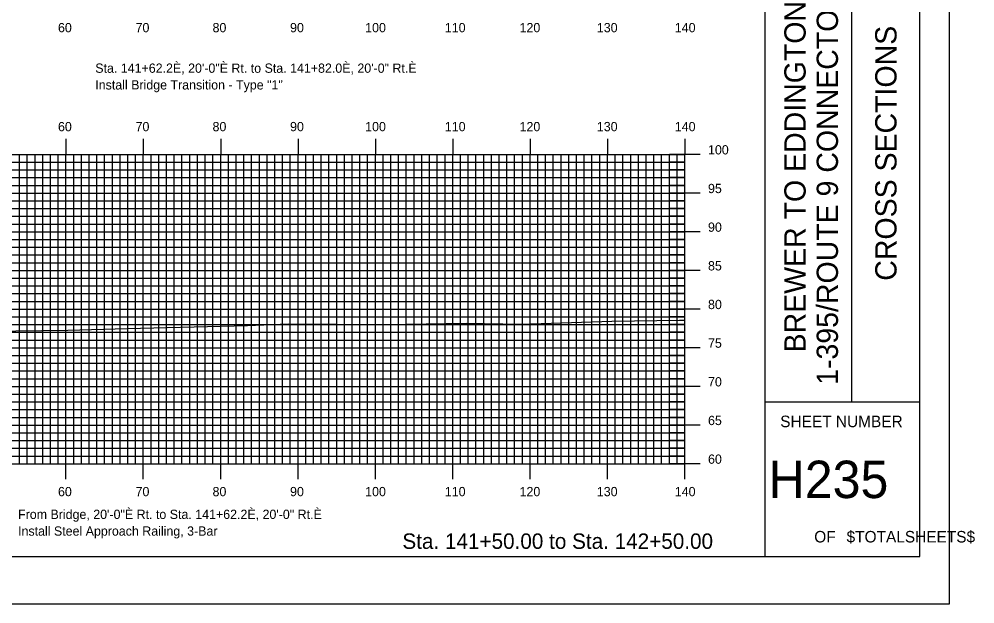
# Model space of a CAD drawing. Extents: x 1776744 to 1777088, y 442591 to 442811.
# Drawn here: x 1776964.2 to 1777087.7, y 442590.5 to 442666.2 of the extents above; entities that cross this region are included whole.
import ezdxf

# ---------------------------------------------------------------- set-up
doc = ezdxf.new("R2010")
doc.units = 0
for name, color, linetype in [('ANNOTATION', 7, 'Continuous'), ('BORDER', 7, 'Continuous'), ('H_V ANNOTATION', 7, 'Continuous'), ('MAJOR', 7, 'Continuous'), ('MINOR', 7, 'Continuous'), ('PLOT BOUNDARY', 7, 'Continuous'), ('S_Roadway_Centerline', 7, 'Continuous')]:
    doc.layers.add(name, color=color, linetype=linetype)

msp = doc.modelspace()

# ---------------------------------------------------------------- linework, layer by layer
at = {"layer": 'BORDER'}
for p, q in [((1777060.65, 442596.67), (1777060.65, 442806.67)), ((1777071.83, 442616.67), (1777071.83, 442686.67)), ((1777060.65, 442616.67), (1777080.65, 442616.67))]:
    msp.add_line(p, q, dxfattribs=at)
msp.add_lwpolyline([(1776760.65, 442596.67), (1777080.65, 442596.67), (1777080.65, 442806.67), (1776760.65, 442806.67)], close=True, dxfattribs=at)
at = {"layer": 'MAJOR'}
for p, q in [((1776970.25, 442650.67), (1776970.25, 442648.67)), ((1776980.25, 442650.67), (1776980.25, 442648.67)), ((1776990.25, 442650.67), (1776990.25, 442648.67)), ((1777000.25, 442650.67), (1777000.25, 442648.67)), ((1777010.25, 442650.67), (1777010.25, 442648.67)), ((1777020.25, 442650.67), (1777020.25, 442648.67)), ((1777030.25, 442650.67), (1777030.25, 442648.67)), ((1777040.25, 442650.67), (1777040.25, 442648.67)), ((1777050.25, 442650.67), (1777050.25, 442648.67)), ((1776770.25, 442648.67), (1777050.25, 442648.67)), ((1776770.25, 442648.67), (1777050.25, 442648.67)), ((1776970.25, 442608.67), (1776970.25, 442648.67)), ((1776980.25, 442608.67), (1776980.25, 442648.67)), ((1776990.25, 442608.67), (1776990.25, 442648.67)), ((1777000.25, 442608.67), (1777000.25, 442648.67)), ((1777010.25, 442608.67), (1777010.25, 442648.67)), ((1777020.25, 442608.67), (1777020.25, 442648.67)), ((1777030.25, 442608.67), (1777030.25, 442648.67)), ((1777040.25, 442608.67), (1777040.25, 442648.67)), ((1777052.25, 442648.67), (1777048.25, 442648.67)), ((1777050.25, 442608.67), (1777050.25, 442648.67)), ((1777050.25, 442608.67), (1777050.25, 442648.67)), ((1776770.25, 442643.67), (1777050.25, 442643.67)), ((1777052.25, 442643.67), (1777048.25, 442643.67)), ((1776770.25, 442638.67), (1777050.25, 442638.67)), ((1777052.25, 442638.67), (1777048.25, 442638.67)), ((1776770.25, 442633.67), (1777050.25, 442633.67)), ((1777052.25, 442633.67), (1777048.25, 442633.67)), ((1776770.25, 442628.67), (1777050.25, 442628.67)), ((1777052.25, 442628.67), (1777048.25, 442628.67)), ((1776770.25, 442623.67), (1777050.25, 442623.67)), ((1777052.25, 442623.67), (1777048.25, 442623.67)), ((1776770.25, 442618.67), (1777050.25, 442618.67)), ((1777052.25, 442618.67), (1777048.25, 442618.67)), ((1776770.25, 442613.67), (1777050.25, 442613.67)), ((1777052.25, 442613.67), (1777048.25, 442613.67)), ((1776770.25, 442608.67), (1777050.25, 442608.67)), ((1776770.25, 442608.67), (1777050.25, 442608.67)), ((1776970.25, 442606.66), (1776970.25, 442608.67)), ((1776980.25, 442606.66), (1776980.25, 442608.67)), ((1776990.25, 442606.66), (1776990.25, 442608.67)), ((1777000.25, 442606.66), (1777000.25, 442608.67)), ((1777010.25, 442606.66), (1777010.25, 442608.67)), ((1777020.25, 442606.66), (1777020.25, 442608.67)), ((1777030.25, 442606.66), (1777030.25, 442608.67)), ((1777040.25, 442606.66), (1777040.25, 442608.67)), ((1777052.25, 442608.67), (1777048.25, 442608.67)), ((1777050.25, 442606.66), (1777050.25, 442608.67))]:
    msp.add_line(p, q, dxfattribs=at)
at = {"layer": 'MINOR'}
for p, q in [((1776964.25, 442608.67), (1776964.25, 442648.67)), ((1776965.25, 442608.67), (1776965.25, 442648.67)), ((1776966.25, 442608.67), (1776966.25, 442648.67)), ((1776967.25, 442608.67), (1776967.25, 442648.67)), ((1776968.25, 442608.67), (1776968.25, 442648.67)), ((1776969.25, 442608.67), (1776969.25, 442648.67)), ((1776971.25, 442608.67), (1776971.25, 442648.67)), ((1776972.25, 442608.67), (1776972.25, 442648.67)), ((1776973.25, 442608.67), (1776973.25, 442648.67)), ((1776974.25, 442608.67), (1776974.25, 442648.67)), ((1776975.25, 442608.67), (1776975.25, 442648.67)), ((1776976.25, 442608.67), (1776976.25, 442648.67)), ((1776977.25, 442608.67), (1776977.25, 442648.67)), ((1776978.25, 442608.67), (1776978.25, 442648.67)), ((1776979.25, 442608.67), (1776979.25, 442648.67)), ((1776981.25, 442608.67), (1776981.25, 442648.67)), ((1776982.25, 442608.67), (1776982.25, 442648.67)), ((1776983.25, 442608.67), (1776983.25, 442648.67)), ((1776984.25, 442608.67), (1776984.25, 442648.67)), ((1776985.25, 442608.67), (1776985.25, 442648.67)), ((1776986.25, 442608.67), (1776986.25, 442648.67)), ((1776987.25, 442608.67), (1776987.25, 442648.67)), ((1776988.25, 442608.67), (1776988.25, 442648.67)), ((1776989.25, 442608.67), (1776989.25, 442648.67)), ((1776991.25, 442608.67), (1776991.25, 442648.67)), ((1776992.25, 442608.67), (1776992.25, 442648.67)), ((1776993.25, 442608.67), (1776993.25, 442648.67)), ((1776994.25, 442608.67), (1776994.25, 442648.67)), ((1776995.25, 442608.67), (1776995.25, 442648.67)), ((1776996.25, 442608.67), (1776996.25, 442648.67)), ((1776997.25, 442608.67), (1776997.25, 442648.67)), ((1776998.25, 442608.67), (1776998.25, 442648.67)), ((1776999.25, 442608.67), (1776999.25, 442648.67)), ((1777001.25, 442608.67), (1777001.25, 442648.67)), ((1777002.25, 442608.67), (1777002.25, 442648.67)), ((1777003.25, 442608.67), (1777003.25, 442648.67)), ((1777004.25, 442608.67), (1777004.25, 442648.67)), ((1777005.25, 442608.67), (1777005.25, 442648.67)), ((1777006.25, 442608.67), (1777006.25, 442648.67)), ((1777007.25, 442608.67), (1777007.25, 442648.67)), ((1777008.25, 442608.67), (1777008.25, 442648.67)), ((1777009.25, 442608.67), (1777009.25, 442648.67)), ((1777011.25, 442608.67), (1777011.25, 442648.67)), ((1777012.25, 442608.67), (1777012.25, 442648.67)), ((1777013.25, 442608.67), (1777013.25, 442648.67)), ((1777014.25, 442608.67), (1777014.25, 442648.67)), ((1777015.25, 442608.67), (1777015.25, 442648.67)), ((1777016.25, 442608.67), (1777016.25, 442648.67)), ((1777017.25, 442608.67), (1777017.25, 442648.67)), ((1777018.25, 442608.67), (1777018.25, 442648.67)), ((1777019.25, 442608.67), (1777019.25, 442648.67)), ((1777021.25, 442608.67), (1777021.25, 442648.67)), ((1777022.25, 442608.67), (1777022.25, 442648.67)), ((1777023.25, 442608.67), (1777023.25, 442648.67)), ((1777024.25, 442608.67), (1777024.25, 442648.67)), ((1777025.25, 442608.67), (1777025.25, 442648.67)), ((1777026.25, 442608.67), (1777026.25, 442648.67)), ((1777027.25, 442608.67), (1777027.25, 442648.67)), ((1777028.25, 442608.67), (1777028.25, 442648.67)), ((1777029.25, 442608.67), (1777029.25, 442648.67)), ((1777031.25, 442608.67), (1777031.25, 442648.67)), ((1777032.25, 442608.67), (1777032.25, 442648.67)), ((1777033.25, 442608.67), (1777033.25, 442648.67)), ((1777034.25, 442608.67), (1777034.25, 442648.67)), ((1777035.25, 442608.67), (1777035.25, 442648.67)), ((1777036.25, 442608.67), (1777036.25, 442648.67)), ((1777037.25, 442608.67), (1777037.25, 442648.67)), ((1777038.25, 442608.67), (1777038.25, 442648.67)), ((1777039.25, 442608.67), (1777039.25, 442648.67)), ((1777041.25, 442608.67), (1777041.25, 442648.67)), ((1777042.25, 442608.67), (1777042.25, 442648.67)), ((1777043.25, 442608.67), (1777043.25, 442648.67)), ((1777044.25, 442608.67), (1777044.25, 442648.67)), ((1777045.25, 442608.67), (1777045.25, 442648.67)), ((1777046.25, 442608.67), (1777046.25, 442648.67)), ((1777047.25, 442608.67), (1777047.25, 442648.67)), ((1777048.25, 442608.67), (1777048.25, 442648.67)), ((1777049.25, 442608.67), (1777049.25, 442648.67)), ((1776770.25, 442647.67), (1777050.25, 442647.67)), ((1777050.25, 442647.67), (1777048.25, 442647.67)), ((1776770.25, 442646.67), (1777050.25, 442646.67)), ((1777050.25, 442646.67), (1777048.25, 442646.67)), ((1776770.25, 442645.67), (1777050.25, 442645.67)), ((1777050.25, 442645.67), (1777048.25, 442645.67)), ((1776770.25, 442644.67), (1777050.25, 442644.67)), ((1777050.25, 442644.67), (1777048.25, 442644.67)), ((1776770.25, 442642.67), (1777050.25, 442642.67)), ((1777050.25, 442642.67), (1777048.25, 442642.67)), ((1776770.25, 442641.67), (1777050.25, 442641.67)), ((1777050.25, 442641.67), (1777048.25, 442641.67)), ((1776770.25, 442640.67), (1777050.25, 442640.67)), ((1777050.25, 442640.67), (1777048.25, 442640.67)), ((1776770.25, 442639.67), (1777050.25, 442639.67)), ((1777050.25, 442639.67), (1777048.25, 442639.67)), ((1776770.25, 442637.67), (1777050.25, 442637.67)), ((1777050.25, 442637.67), (1777048.25, 442637.67)), ((1776770.25, 442636.67), (1777050.25, 442636.67)), ((1777050.25, 442636.67), (1777048.25, 442636.67)), ((1776770.25, 442635.67), (1777050.25, 442635.67)), ((1777050.25, 442635.67), (1777048.25, 442635.67)), ((1776770.25, 442634.67), (1777050.25, 442634.67)), ((1777050.25, 442634.67), (1777048.25, 442634.67)), ((1776770.25, 442632.67), (1777050.25, 442632.67)), ((1777050.25, 442632.67), (1777048.25, 442632.67)), ((1776770.25, 442631.67), (1777050.25, 442631.67)), ((1777050.25, 442631.67), (1777048.25, 442631.67)), ((1776770.25, 442630.67), (1777050.25, 442630.67)), ((1777050.25, 442630.67), (1777048.25, 442630.67)), ((1776770.25, 442629.67), (1777050.25, 442629.67)), ((1777050.25, 442629.67), (1777048.25, 442629.67)), ((1776770.25, 442627.67), (1777050.25, 442627.67)), ((1777050.25, 442627.67), (1777048.25, 442627.67)), ((1776770.25, 442626.67), (1777050.25, 442626.67)), ((1777050.25, 442626.67), (1777048.25, 442626.67)), ((1776770.25, 442625.67), (1777050.25, 442625.67)), ((1777050.25, 442625.67), (1777048.25, 442625.67)), ((1776770.25, 442624.67), (1777050.25, 442624.67)), ((1777050.25, 442624.67), (1777048.25, 442624.67)), ((1776770.25, 442622.67), (1777050.25, 442622.67)), ((1777050.25, 442622.67), (1777048.25, 442622.67)), ((1776770.25, 442621.67), (1777050.25, 442621.67)), ((1777050.25, 442621.67), (1777048.25, 442621.67)), ((1776770.25, 442620.67), (1777050.25, 442620.67)), ((1777050.25, 442620.67), (1777048.25, 442620.67)), ((1776770.25, 442619.67), (1777050.25, 442619.67)), ((1777050.25, 442619.67), (1777048.25, 442619.67)), ((1776770.25, 442617.67), (1777050.25, 442617.67)), ((1777050.25, 442617.67), (1777048.25, 442617.67)), ((1776770.25, 442616.67), (1777050.25, 442616.67)), ((1777050.25, 442616.67), (1777048.25, 442616.67)), ((1776770.25, 442615.67), (1777050.25, 442615.67)), ((1777050.25, 442615.67), (1777048.25, 442615.67)), ((1776770.25, 442614.67), (1777050.25, 442614.67)), ((1777050.25, 442614.67), (1777048.25, 442614.67)), ((1776770.25, 442612.67), (1777050.25, 442612.67)), ((1777050.25, 442612.67), (1777048.25, 442612.67)), ((1776770.25, 442611.67), (1777050.25, 442611.67)), ((1777050.25, 442611.67), (1777048.25, 442611.67)), ((1776770.25, 442610.67), (1777050.25, 442610.67)), ((1777050.25, 442610.67), (1777048.25, 442610.67)), ((1776770.25, 442609.67), (1777050.25, 442609.67)), ((1777050.25, 442609.67), (1777048.25, 442609.67))]:
    msp.add_line(p, q, dxfattribs=at)
at = {"layer": 'PLOT BOUNDARY'}
msp.add_lwpolyline([(1776744.46, 442590.55), (1777084.46, 442590.55), (1777084.46, 442810.55), (1776744.46, 442810.55)], close=True, dxfattribs=at)
at = {"layer": 'S_Roadway_Centerline'}
msp.add_lwpolyline([(1776957.01, 442625.77), (1776970.51, 442625.95), (1776978.17, 442626.18), (1776993.7, 442626.55), (1776998.99, 442626.75), (1777011.55, 442626.68), (1777022.04, 442626.86), (1777029.04, 442626.73), (1777040.82, 442627.09), (1777049.58, 442627.26), (1777050.25, 442627.25)], dxfattribs=at)

# ---------------------------------------------------------------- texts
at = {"layer": 'ANNOTATION'}
for s, p in [('Sta. 141+62.2È, 20\'-0"È Rt. to Sta. 141+82.0È, 20\'-0" Rt.È', (1776974.04, 442659.23)), ('Install Bridge Transition - Type "1"', (1776974.04, 442657.07)), ('From Bridge, 20\'-0"È Rt. to Sta. 141+62.2È, 20\'-0" Rt.È', (1776964.06, 442601.53)), ('Install Steel Approach Railing, 3-Bar', (1776964.06, 442599.37))]:
    msp.add_text(s, height=1.2, dxfattribs=at).set_placement(p)
at = {"layer": 'BORDER'}
for s, p in [('1-395/ROUTE 9 CONNECTOR', (1777070.05, 442618.87)), ('BREWER TO EDDINGTON', (1777065.87, 442623.07)), ('CROSS SECTIONS', (1777077.62, 442632.34))]:
    msp.add_text(s, height=2.7557, rotation=90, dxfattribs=at).set_placement(p)
for s, height, p in [('SHEET NUMBER', 1.4905, (1777062.58, 442613.4)), ('H235', 4.839, (1777061.09, 442604.23)), ('OF', 1.491, (1777066.98, 442598.49)), ('$TOTALSHEETS$', 1.4905, (1777071.16, 442598.49))]:
    msp.add_text(s, height=height, dxfattribs=at).set_placement(p)
at = {"layer": 'H_V ANNOTATION'}
for s, height, p in [('60', 1.2, (1776969.22, 442664.47)), ('70', 1.2, (1776979.25, 442664.47)), ('80', 1.2, (1776989.2, 442664.47)), ('90', 1.2, (1776999.22, 442664.47)), ('100', 1.2, (1777008.93, 442664.47)), ('110', 1.2, (1777019.23, 442664.47)), ('120', 1.2, (1777028.89, 442664.47)), ('130', 1.2, (1777038.88, 442664.47)), ('140', 1.2, (1777048.96, 442664.47)), ('60', 1.2, (1776969.22, 442651.67)), ('70', 1.2, (1776979.25, 442651.67)), ('80', 1.2, (1776989.2, 442651.67)), ('90', 1.2, (1776999.22, 442651.67)), ('100', 1.2, (1777008.93, 442651.67)), ('110', 1.2, (1777019.23, 442651.67)), ('120', 1.2, (1777028.89, 442651.67)), ('130', 1.2, (1777038.88, 442651.67)), ('140', 1.2, (1777048.96, 442651.67)), ('100', 1.2, (1777053.25, 442648.67)), ('95', 1.2, (1777053.25, 442643.67)), ('90', 1.2, (1777053.25, 442638.67)), ('85', 1.2, (1777053.25, 442633.67)), ('80', 1.2, (1777053.25, 442628.67)), ('75', 1.2, (1777053.25, 442623.67)), ('70', 1.2, (1777053.25, 442618.67)), ('65', 1.2, (1777053.25, 442613.67)), ('60', 1.2, (1777053.25, 442608.67)), ('60', 1.2, (1776969.22, 442604.47)), ('70', 1.2, (1776979.25, 442604.47)), ('80', 1.2, (1776989.2, 442604.47)), ('90', 1.2, (1776999.22, 442604.47)), ('100', 1.2, (1777008.93, 442604.47)), ('110', 1.2, (1777019.23, 442604.47)), ('120', 1.2, (1777028.89, 442604.47)), ('130', 1.2, (1777038.88, 442604.47)), ('140', 1.2, (1777048.96, 442604.47)), ('Sta. 141+50.00 to Sta. 142+50.00', 2.0004, (1777013.74, 442597.66))]:
    msp.add_text(s, height=height, dxfattribs=at).set_placement(p)

doc.saveas('drawing.dxf')
